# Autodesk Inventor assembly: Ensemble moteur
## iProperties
Shininess: 41.0
Length Units: 11269
Angle Units: 11279
Time Units: 11290
Mass Units: 11283
Length Display Precision: 3
Angle Display Precision: 2
Created: 2002-11
Part Number: Ensemble moteur
Document SubType Name: Assemblage
Designer: poste-2
Density: 0.0
Volumn: 0.0
Area: 0.0
PropertySet Name: Model Information
Control State: 0
Master: False
Checked Out: False
Author: poste-2
